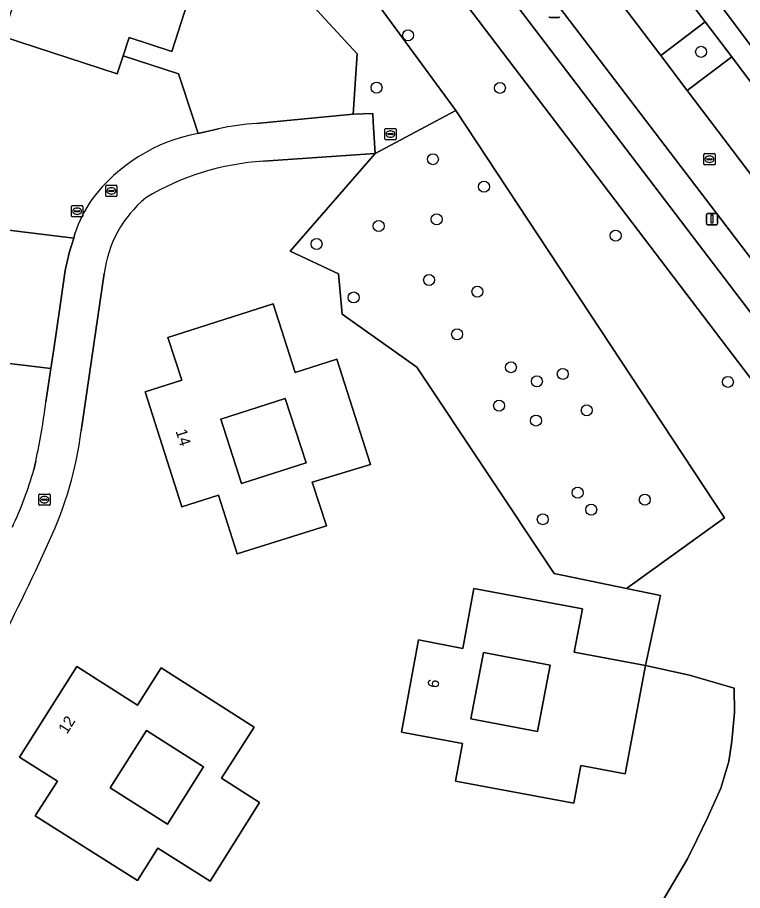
# Model space of a CAD drawing. Extents: x 156661 to 157576, y 383570 to 384425.
# Drawn here: x 156857.2 to 156921.7, y 384130.7 to 384208.3 of the extents above; entities that cross this region are included whole.
import ezdxf

# ---------------------------------------------------------------- set-up
doc = ezdxf.new("R2010")
doc.units = 0
for name, color, linetype in [('IMGEO_Berm_groen', 7, 'Continuous'), ('IMGEO_Boom', 7, 'Continuous'), ('IMGEO_Brandkraan', 7, 'Continuous'), ('IMGEO_Erf', 7, 'Continuous'), ('IMGEO_Fietspad_gesloten', 7, 'Continuous'), ('IMGEO_Groenvoorziening', 7, 'Continuous'), ('IMGEO_Lichtmast', 7, 'Continuous'), ('IMGEO_Loofbos', 7, 'Continuous'), ('IMGEO_Pand', 7, 'Continuous'), ('IMGEO_Pand_nummerreeks', 7, 'Continuous'), ('IMGEO_Parkeervlak_open', 7, 'Continuous'), ('IMGEO_Rijbaan_lokaal_gesloten', 7, 'Continuous'), ('IMGEO_Rioolput', 7, 'Continuous'), ('IMGEO_Voetpad_open', 7, 'Continuous')]:
    doc.layers.add(name, color=color, linetype=linetype)

msp = doc.modelspace()

# ---------------------------------------------------------------- linework, layer by layer
at = {"layer": 'IMGEO_Berm_groen'}
msp.add_lwpolyline([(156867.867, 384253.653), (156927.81, 384174.952), (156945.927, 384151.336), (156948.198, 384153.058), (156947.883, 384153.474), (156869.636, 384256.091)], dxfattribs=at)
msp.add_lwpolyline([(156918.348, 384207.896), (156914.397, 384204.906), (156916.761, 384201.782), (156920.708, 384204.77)], close=True, dxfattribs=at)
at = {"layer": 'IMGEO_Boom'}
for centre in [(156891.939, 384206.689), (156917.988, 384205.227), (156889.136, 384202.044), (156900.103, 384202.022), (156894.148, 384195.688), (156898.69, 384193.242), (156889.319, 384189.747), (156894.485, 384190.346), (156910.399, 384188.893), (156883.802, 384188.145), (156893.807, 384184.951), (156887.103, 384183.396), (156898.103, 384183.916), (156896.299, 384180.124), (156901.082, 384177.196), (156905.693, 384176.603), (156903.39, 384175.94), (156920.375, 384175.898), (156900.031, 384173.783), (156907.826, 384173.368), (156903.311, 384172.461), (156907.022, 384166.05), (156912.986, 384165.427), (156908.22, 384164.535), (156903.918, 384163.688)]:
    msp.add_circle(centre, 0.489, dxfattribs=at)
at = {"layer": 'IMGEO_Brandkraan'}
for p, q in [((156862.015, 384190.633), (156862.015, 384191.485)), ((156862.09, 384191.559), (156862.942, 384191.559)), ((156862.274, 384191.053), (156862.274, 384191.065)), ((156862.712, 384191.016), (156862.314, 384191.016)), ((156862.317, 384191.102), (156862.715, 384191.102)), ((156862.503, 384191.339), (156862.528, 384191.339)), ((156862.758, 384191.065), (156862.758, 384191.053)), ((156863.016, 384191.485), (156863.016, 384190.633)), ((156862.942, 384190.559), (156862.09, 384190.559)), ((156862.526, 384190.779), (156862.501, 384190.779))]:
    msp.add_line(p, q, dxfattribs=at)
for points in [[(156862.015, 384190.633), (156862.015, 384191.485)], [(156862.09, 384191.559), (156862.942, 384191.559)], [(156863.016, 384191.485), (156863.016, 384190.633)], [(156862.942, 384190.559), (156862.09, 384190.559)]]:
    msp.add_lwpolyline(points, dxfattribs=at)
for centre, radius, start, end in [((156862.092, 384191.483), 0.0765, 91.55205, 178.44795), ((156862.092, 384191.483), 0.0765, 91.55205, 178.44795), ((156862.314, 384191.062), 0.0403, 85.87752, 175.75265), ((156862.311, 384191.052), 0.0366, 178.93798, 274.71019), ((156862.715, 384191.059), 0.043, 264.86636, 352.45326), ((156862.719, 384191.064), 0.0386, 1.73085, 96.63898), ((156862.94, 384191.483), 0.0765, 1.55205, 88.44795), ((156862.94, 384191.483), 0.0765, 1.55205, 88.44795), ((156862.092, 384190.635), 0.0765, 181.55205, 268.44795), ((156862.092, 384190.635), 0.0765, 181.55205, 268.44795), ((156862.94, 384190.635), 0.0765, 271.55205, 358.44795), ((156862.94, 384190.635), 0.0765, 271.55205, 358.44795)]:
    msp.add_arc(centre, radius, start, end, dxfattribs=at)
for centre, major_axis, ratio, start_param, end_param in [((156862.502, 384191.059), (-0.387, 0.002), 0.722429, 4.712389, 7.853982), ((156862.527, 384191.059), (-0.39, 0.002), 0.717154, 1.570796, 4.712389)]:
    msp.add_ellipse(centre, major_axis=major_axis, ratio=ratio, start_param=start_param, end_param=end_param, dxfattribs=at)
at = {"layer": 'IMGEO_Erf'}
for points in [[(156873.961, 384214.559), (156872.032, 384208.65), (156870.925, 384205.255), (156867.13, 384206.495), (156866.597, 384204.873), (156871.527, 384203.266), (156872.855, 384199.253), (156873.276, 384197.981), (156875.087, 384198.385)], [(156878.469, 384198.871), (156880.897, 384199.085), (156887.053, 384199.698), (156887.401, 384205.04), (156880.686, 384212.359), (156873.961, 384214.559)], [(156913.042, 384150.679), (156914.369, 384156.907), (156911.353, 384157.536), (156904.931, 384158.876), (156892.709, 384177.194), (156886.083, 384181.928), (156885.768, 384185.506), (156881.456, 384187.505), (156889.009, 384196.195), (156879.074, 384195.504)], [(156864.923, 384185.542), (156862.886, 384171.545)], [(156911.232, 384109.029), (156911.053, 384109.423), (156910.897, 384109.877), (156909.839, 384114.445), (156909.514, 384116.775), (156909.382, 384117.878), (156909.426, 384118.952), (156909.558, 384119.746), (156910.294, 384122.041), (156911.324, 384124.31), (156916.768, 384133.516), (156917.618, 384135.197), (156918.56, 384137.15), (156919.737, 384139.785), (156920.467, 384142.161), (156920.715, 384143.965), (156920.951, 384146.515), (156920.928, 384148.664), (156916.959, 384149.844), (156913.042, 384150.679)]]:
    msp.add_lwpolyline(points, dxfattribs=at)
for points in [[(156862.225, 384188.659), (156855.43, 384189.495), (156854.647, 384183.209), (156854.186, 384179.514), (156850.228, 384180.007), (156850.013, 384178.291), (156860.187, 384177.083), (156860.435, 384178.797), (156860.969, 384182.483), (156861.466, 384185.786), (156861.796, 384187.367)], [(156876.751, 384160.602), (156875.084, 384165.84), (156871.829, 384164.801), (156868.572, 384175.009), (156871.827, 384176.044), (156870.583, 384179.841), (156879.937, 384182.83), (156881.895, 384176.737), (156885.611, 384177.916), (156888.599, 384168.555), (156883.415, 384166.995), (156884.673, 384163.097)], [(156882.865, 384168.698), (156881.016, 384174.427), (156875.293, 384172.58), (156877.142, 384166.851)], [(156896.154, 384140.409), (156896.776, 384143.771), (156891.354, 384144.753), (156892.871, 384152.959), (156896.804, 384152.211), (156897.796, 384157.534), (156907.432, 384155.736), (156906.712, 384151.876), (156913.042, 384150.679), (156911.225, 384141.066), (156907.289, 384141.798), (156906.669, 384138.463)], [(156898.652, 384151.859), (156897.528, 384145.952), (156903.443, 384144.827), (156904.567, 384150.734)], [(156875.351, 384140.668), (156878.732, 384138.517), (156874.338, 384131.527), (156869.687, 384134.452), (156867.875, 384131.591), (156858.8, 384137.317), (156860.766, 384140.413), (156857.394, 384142.547), (156862.49, 384150.597), (156867.874, 384147.177), (156869.985, 384150.476), (156878.247, 384145.221)], [(156870.54, 384136.603), (156873.766, 384141.676), (156868.688, 384144.906), (156865.461, 384139.833)]]:
    msp.add_lwpolyline(points, close=True, dxfattribs=at)
for centre, radius, start, end in [((156880.252, 384174.455), 24.481, 94.17602, 102.17905), ((156880.467, 384172.559), 22.987, 93.47345, 121.04804), ((156875.318, 384184.198), 10.481, 129.78358, 172.63482), ((156830.416, 384175.686), 32.733, 334.78913, 352.73266), ((156700.922, 384232.989), 174.332, 332.10301, 335.87805)]:
    msp.add_arc(centre, radius, start, end, dxfattribs=at)
at = {"layer": 'IMGEO_Fietspad_gesloten'}
for points in [[(156867.867, 384253.653), (156865.71, 384256.504), (156841.833, 384287.919), (156840.64, 384289.505), (156837.709, 384287.416), (156838.979, 384285.829), (156848.127, 384273.808), (156849.254, 384272.327), (156925.032, 384172.754), (156949.045, 384141.371)], [(156950.51, 384145.361), (156946.909, 384150.056), (156945.927, 384151.336), (156927.81, 384174.952), (156867.867, 384253.653)]]:
    msp.add_lwpolyline(points, dxfattribs=at)
at = {"layer": 'IMGEO_Groenvoorziening'}
for points in [[(156949.045, 384141.371), (156925.032, 384172.754), (156849.254, 384272.327)], [(156848.981, 384271.579), (156849.06, 384268.625), (156849.604, 384262.282), (156851.427, 384260.941), (156896.18, 384200.013), (156920.073, 384163.8), (156911.353, 384157.536), (156914.369, 384156.907), (156913.042, 384150.679), (156916.959, 384149.844), (156920.928, 384148.664), (156920.951, 384146.515), (156920.715, 384143.965), (156920.467, 384142.161), (156919.737, 384139.785), (156918.56, 384137.15), (156917.618, 384135.197), (156916.768, 384133.516), (156911.324, 384124.31)], [(156879.806, 384262.53), (156939.02, 384183.696)], [(156854.296, 384219.378), (156858.108, 384218.134), (156859.786, 384223.277), (156869.084, 384220.243), (156867.877, 384216.545), (156873.961, 384214.559), (156880.686, 384212.359), (156887.401, 384205.04), (156887.053, 384199.698), (156888.801, 384199.741), (156888.846, 384198.97), (156889.009, 384196.195), (156896.18, 384200.013), (156851.427, 384260.941)], [(156873.276, 384197.981), (156872.855, 384199.253), (156871.527, 384203.266), (156866.597, 384204.873), (156866.069, 384203.268), (156855.917, 384206.59)], [(156859.745, 384174.109), (156860.187, 384177.083), (156850.013, 384178.291), (156849.805, 384176.629), (156839.204, 384177.937), (156839.62, 384181.311), (156834.165, 384181.975), (156835.167, 384190.214), (156839.154, 384189.729), (156839.855, 384195.355), (156849.56, 384194.146), (156849.079, 384190.286), (156855.43, 384189.495), (156862.225, 384188.659), (156862.308, 384189.069)], [(156858.67, 384168.076), (156858.839, 384168.84)]]:
    msp.add_lwpolyline(points, dxfattribs=at)
for centre, radius, start, end in [((156876.099, 384182.888), 15.355, 100.59367, 143.05005), ((156874.161, 384185.063), 12.512, 145.67788, 161.3274), ((156797.327, 384182.129), 62.932, 347.80895, 352.67795), ((156824.03, 384178.186), 36.085, 335.09667, 343.72952)]:
    msp.add_arc(centre, radius, start, end, dxfattribs=at)
at = {"layer": 'IMGEO_Lichtmast'}
for p, q in [((156905.343, 384208.281), (156904.553, 384208.281)), ((156904.553, 384208.281), (156905.343, 384208.281)), ((156918.561, 384190.862), (156919.351, 384190.862)), ((156919.351, 384190.862), (156918.561, 384190.862)), ((156918.461, 384189.962), (156918.461, 384190.762)), ((156918.461, 384190.762), (156918.461, 384189.962)), ((156919.451, 384190.762), (156919.451, 384189.962)), ((156919.451, 384189.962), (156919.451, 384190.762)), ((156919.351, 384189.862), (156918.561, 384189.862)), ((156918.561, 384189.862), (156919.351, 384189.862))]:
    msp.add_line(p, q, dxfattribs=at)
msp.add_lwpolyline([(156918.881, 384190.737), (156919.031, 384190.737), (156919.031, 384189.987), (156918.881, 384189.987), (156918.881, 384190.737)], dxfattribs=at)
for centre, start, end in [((156904.553, 384208.381), 180, 270), ((156904.553, 384208.381), 180, 270), ((156905.343, 384208.381), 270, 0), ((156905.343, 384208.381), 270, 0), ((156918.561, 384190.762), 90, 180), ((156918.561, 384190.762), 90, 180), ((156919.351, 384190.762), 0, 90), ((156919.351, 384190.762), 360, 90), ((156918.561, 384189.962), 180, 270), ((156918.561, 384189.962), 180, 270), ((156919.351, 384189.962), 270, 0), ((156919.351, 384189.962), 270, 0)]:
    msp.add_arc(centre, 0.1, start, end, dxfattribs=at)
at = {"layer": 'IMGEO_Loofbos'}
msp.add_lwpolyline([(156881.456, 384187.505), (156885.768, 384185.506), (156886.083, 384181.928), (156892.709, 384177.194), (156904.931, 384158.876), (156911.353, 384157.536), (156920.073, 384163.8), (156896.18, 384200.013), (156889.009, 384196.195)], close=True, dxfattribs=at)
at = {"layer": 'IMGEO_Pand'}
for points in [[(156873.961, 384214.559), (156867.877, 384216.545), (156869.084, 384220.243), (156859.786, 384223.277), (156858.108, 384218.134), (156854.296, 384219.378), (156851.734, 384211.527), (156856.974, 384209.822), (156855.917, 384206.59), (156866.069, 384203.268), (156866.597, 384204.873), (156867.13, 384206.495), (156870.925, 384205.255), (156872.032, 384208.65)], [(156885.611, 384177.916), (156881.895, 384176.737), (156879.937, 384182.83), (156870.583, 384179.841), (156871.827, 384176.044), (156868.572, 384175.009), (156871.829, 384164.801), (156875.084, 384165.84), (156876.751, 384160.602), (156884.673, 384163.097), (156883.415, 384166.995), (156888.599, 384168.555)], [(156882.865, 384168.698), (156877.142, 384166.851), (156875.293, 384172.58), (156881.016, 384174.427)], [(156913.042, 384150.679), (156906.712, 384151.876), (156907.432, 384155.736), (156897.796, 384157.534), (156896.804, 384152.211), (156892.871, 384152.959), (156891.354, 384144.753), (156896.776, 384143.771), (156896.154, 384140.409), (156906.669, 384138.463), (156907.289, 384141.798), (156911.225, 384141.066)], [(156898.652, 384151.859), (156904.567, 384150.734), (156903.443, 384144.827), (156897.528, 384145.952)], [(156878.247, 384145.221), (156869.985, 384150.476), (156867.874, 384147.177), (156862.49, 384150.597), (156857.394, 384142.547), (156860.766, 384140.413), (156858.8, 384137.317), (156867.875, 384131.591), (156869.687, 384134.452), (156874.338, 384131.527), (156878.732, 384138.517), (156875.351, 384140.668)], [(156870.54, 384136.603), (156865.461, 384139.833), (156868.688, 384144.906), (156873.766, 384141.676)]]:
    msp.add_lwpolyline(points, close=True, dxfattribs=at)
at = {"layer": 'IMGEO_Parkeervlak_open'}
for points in [[(156914.397, 384204.906), (156918.348, 384207.896), (156909.04, 384220.251), (156905.044, 384217.212)], [(156926.719, 384196.787), (156920.708, 384204.77), (156916.761, 384201.782), (156922.806, 384193.826)]]:
    msp.add_lwpolyline(points, close=True, dxfattribs=at)
at = {"layer": 'IMGEO_Rijbaan_lokaal_gesloten'}
for points in [[(156876.48, 384254.755), (156868.186, 384265.651), (156860.937, 384275.173), (156857.345, 384272.328), (156868.344, 384257.78), (156869.636, 384256.091), (156947.883, 384153.474), (156948.198, 384153.058), (156949.137, 384151.82), (156967.768, 384127.243)], [(156978.939, 384120.025), (156978.024, 384121.227), (156977.753, 384121.583), (156976.126, 384123.722), (156968.544, 384133.691), (156965.332, 384137.913), (156955.947, 384150.252), (156954.053, 384152.742), (156952.237, 384155.208), (156949.248, 384159.24), (156941.651, 384169.047), (156938.611, 384173.044), (156935.139, 384177.608), (156933.628, 384179.594), (156922.806, 384193.826), (156916.761, 384201.782), (156914.397, 384204.906), (156905.044, 384217.212), (156901.645, 384221.683), (156891.001, 384235.643), (156888.996, 384238.303), (156878.44, 384252.173), (156876.735, 384254.42)], [(156879.074, 384195.504), (156889.009, 384196.195), (156888.846, 384198.97), (156888.801, 384199.741), (156887.053, 384199.698), (156880.897, 384199.085), (156878.469, 384198.871)], [(156875.087, 384198.385), (156873.276, 384197.981)], [(156862.308, 384189.069), (156862.225, 384188.659), (156861.796, 384187.367), (156861.466, 384185.786), (156860.969, 384182.483), (156860.435, 384178.797), (156860.187, 384177.083), (156859.745, 384174.109)], [(156862.886, 384171.545), (156864.923, 384185.542)], [(156858.839, 384168.84), (156858.67, 384168.076)]]:
    msp.add_lwpolyline(points, dxfattribs=at)
for centre, radius, start, end in [((156880.252, 384174.455), 24.481, 94.17602, 102.17905), ((156876.099, 384182.888), 15.355, 100.59367, 143.05005), ((156880.467, 384172.559), 22.987, 93.47345, 121.04804), ((156874.161, 384185.063), 12.512, 145.67788, 161.3274), ((156875.318, 384184.198), 10.481, 129.78358, 172.63482), ((156797.327, 384182.129), 62.932, 347.80895, 352.67795), ((156830.416, 384175.686), 32.733, 334.78913, 352.73266), ((156824.03, 384178.186), 36.085, 335.09667, 343.72952), ((156700.922, 384232.989), 174.332, 332.10301, 335.87805)]:
    msp.add_arc(centre, radius, start, end, dxfattribs=at)
at = {"layer": 'IMGEO_Rioolput'}
for p, q in [((156889.867, 384197.491), (156889.867, 384198.343)), ((156889.942, 384198.417), (156890.794, 384198.417)), ((156890.126, 384197.911), (156890.126, 384197.923)), ((156890.564, 384197.874), (156890.166, 384197.874)), ((156890.169, 384197.96), (156890.567, 384197.96)), ((156890.355, 384198.197), (156890.38, 384198.197)), ((156890.61, 384197.923), (156890.61, 384197.911)), ((156890.868, 384198.343), (156890.868, 384197.491)), ((156890.794, 384197.417), (156889.942, 384197.417)), ((156890.378, 384197.637), (156890.353, 384197.637)), ((156918.234, 384195.255), (156918.234, 384196.107)), ((156918.309, 384196.181), (156919.161, 384196.181)), ((156918.493, 384195.675), (156918.493, 384195.687)), ((156918.931, 384195.638), (156918.533, 384195.638)), ((156918.536, 384195.724), (156918.934, 384195.724)), ((156918.722, 384195.961), (156918.747, 384195.961)), ((156918.977, 384195.687), (156918.977, 384195.675)), ((156919.235, 384196.107), (156919.235, 384195.255)), ((156919.161, 384195.181), (156918.309, 384195.181)), ((156918.745, 384195.401), (156918.72, 384195.401)), ((156865.059, 384192.443), (156865.059, 384193.295)), ((156865.134, 384193.369), (156865.986, 384193.369)), ((156866.06, 384193.295), (156866.06, 384192.443)), ((156865.318, 384192.863), (156865.318, 384192.875)), ((156865.756, 384192.826), (156865.358, 384192.826)), ((156865.361, 384192.912), (156865.759, 384192.912)), ((156865.57, 384192.589), (156865.545, 384192.589)), ((156865.547, 384193.149), (156865.572, 384193.149)), ((156865.802, 384192.875), (156865.802, 384192.863)), ((156865.986, 384192.369), (156865.134, 384192.369)), ((156859.107, 384165.002), (156859.107, 384165.854)), ((156859.182, 384165.928), (156860.034, 384165.928)), ((156859.366, 384165.422), (156859.366, 384165.434)), ((156859.804, 384165.385), (156859.406, 384165.385)), ((156859.409, 384165.471), (156859.807, 384165.471)), ((156859.595, 384165.708), (156859.62, 384165.708)), ((156859.85, 384165.434), (156859.85, 384165.422)), ((156860.108, 384165.854), (156860.108, 384165.002)), ((156860.034, 384164.928), (156859.182, 384164.928)), ((156859.618, 384165.148), (156859.593, 384165.148))]:
    msp.add_line(p, q, dxfattribs=at)
for points in [[(156889.867, 384197.491), (156889.867, 384198.343)], [(156889.942, 384198.417), (156890.794, 384198.417)], [(156890.868, 384198.343), (156890.868, 384197.491)], [(156890.794, 384197.417), (156889.942, 384197.417)], [(156918.234, 384195.255), (156918.234, 384196.107)], [(156918.309, 384196.181), (156919.161, 384196.181)], [(156919.235, 384196.107), (156919.235, 384195.255)], [(156919.161, 384195.181), (156918.309, 384195.181)], [(156865.059, 384192.443), (156865.059, 384193.295)], [(156865.134, 384193.369), (156865.986, 384193.369)], [(156866.06, 384193.295), (156866.06, 384192.443)], [(156865.986, 384192.369), (156865.134, 384192.369)], [(156859.107, 384165.002), (156859.107, 384165.854)], [(156859.182, 384165.928), (156860.034, 384165.928)], [(156860.108, 384165.854), (156860.108, 384165.002)], [(156860.034, 384164.928), (156859.182, 384164.928)]]:
    msp.add_lwpolyline(points, dxfattribs=at)
for centre, radius, start, end in [((156889.944, 384198.341), 0.0765, 91.55205, 178.44795), ((156889.944, 384198.341), 0.0765, 91.55205, 178.44795), ((156890.166, 384197.92), 0.0403, 85.87752, 175.75265), ((156890.163, 384197.91), 0.0366, 178.93798, 274.71019), ((156890.567, 384197.917), 0.043, 264.86636, 352.45326), ((156890.571, 384197.922), 0.0386, 1.73085, 96.63898), ((156890.792, 384198.341), 0.0765, 1.55205, 88.44795), ((156890.792, 384198.341), 0.0765, 1.55205, 88.44795), ((156889.944, 384197.493), 0.0765, 181.55205, 268.44795), ((156889.944, 384197.493), 0.0765, 181.55205, 268.44795), ((156890.792, 384197.493), 0.0765, 271.55205, 358.44795), ((156890.792, 384197.493), 0.0765, 271.55205, 358.44795), ((156918.311, 384196.105), 0.0765, 91.55205, 178.44795), ((156918.311, 384196.105), 0.0765, 91.55205, 178.44795), ((156918.533, 384195.684), 0.0403, 85.87752, 175.75265), ((156918.53, 384195.674), 0.0366, 178.93798, 274.71019), ((156918.934, 384195.681), 0.043, 264.86636, 352.45326), ((156918.938, 384195.686), 0.0386, 1.73085, 96.63898), ((156919.159, 384196.105), 0.0765, 1.55205, 88.44795), ((156919.159, 384196.105), 0.0765, 1.55205, 88.44795), ((156918.311, 384195.257), 0.0765, 181.55205, 268.44795), ((156918.311, 384195.257), 0.0765, 181.55205, 268.44795), ((156919.159, 384195.257), 0.0765, 271.55205, 358.44795), ((156919.159, 384195.257), 0.0765, 271.55205, 358.44795), ((156865.136, 384193.293), 0.0765, 91.55205, 178.44795), ((156865.136, 384193.293), 0.0765, 91.55205, 178.44795), ((156865.984, 384193.293), 0.0765, 1.55205, 88.44795), ((156865.984, 384193.293), 0.0765, 1.55205, 88.44795), ((156865.136, 384192.445), 0.0765, 181.55205, 268.44795), ((156865.136, 384192.445), 0.0765, 181.55205, 268.44795), ((156865.358, 384192.872), 0.0403, 85.87752, 175.75265), ((156865.355, 384192.862), 0.0366, 178.93798, 274.71019), ((156865.759, 384192.869), 0.043, 264.86636, 352.45326), ((156865.763, 384192.874), 0.0386, 1.73085, 96.63898), ((156865.984, 384192.445), 0.0765, 271.55205, 358.44795), ((156865.984, 384192.445), 0.0765, 271.55205, 358.44795), ((156859.184, 384165.852), 0.0765, 91.55205, 178.44795), ((156859.184, 384165.852), 0.0765, 91.55205, 178.44795), ((156859.406, 384165.431), 0.0403, 85.87752, 175.75265), ((156859.403, 384165.421), 0.0366, 178.93798, 274.71019), ((156859.807, 384165.428), 0.043, 264.86636, 352.45326), ((156859.811, 384165.433), 0.0386, 1.73085, 96.63898), ((156860.032, 384165.852), 0.0765, 1.55205, 88.44795), ((156860.032, 384165.852), 0.0765, 1.55205, 88.44795), ((156859.184, 384165.004), 0.0765, 181.55205, 268.44795), ((156859.184, 384165.004), 0.0765, 181.55205, 268.44795), ((156860.032, 384165.004), 0.0765, 271.55205, 358.44795), ((156860.032, 384165.004), 0.0765, 271.55205, 358.44795)]:
    msp.add_arc(centre, radius, start, end, dxfattribs=at)
for centre, major_axis, ratio, start_param, end_param in [((156890.354, 384197.917), (-0.387, 0.002), 0.722429, 4.712389, 7.853982), ((156890.379, 384197.917), (-0.39, 0.002), 0.717154, 1.570796, 4.712389), ((156918.721, 384195.681), (-0.387, 0.002), 0.722429, 4.712389, 7.853982), ((156918.746, 384195.681), (-0.39, 0.002), 0.717154, 1.570796, 4.712389), ((156865.546, 384192.869), (-0.387, 0.002), 0.722429, 4.712389, 7.853982), ((156865.571, 384192.869), (-0.39, 0.002), 0.717154, 1.570796, 4.712389), ((156859.594, 384165.428), (-0.387, 0.002), 0.722429, 4.712389, 7.853982), ((156859.619, 384165.428), (-0.39, 0.002), 0.717154, 1.570796, 4.712389)]:
    msp.add_ellipse(centre, major_axis=major_axis, ratio=ratio, start_param=start_param, end_param=end_param, dxfattribs=at)
at = {"layer": 'IMGEO_Voetpad_open'}
for points in [[(156983.009, 384125.143), (156960.044, 384155.717), (156957.136, 384159.589), (156954.003, 384163.76), (156953.814, 384164.012), (156946.64, 384173.562), (156943.34, 384177.955), (156939.02, 384183.696), (156879.806, 384262.53), (156876.187, 384267.345), (156852.753, 384298.627)], [(156852.393, 384295.853), (156865.294, 384278.622), (156874.701, 384266.057), (156878.321, 384261.237), (156882.665, 384255.414), (156893.129, 384241.435), (156895.163, 384238.727), (156905.644, 384224.752), (156909.04, 384220.251), (156918.348, 384207.896), (156920.708, 384204.77), (156926.719, 384196.787), (156937.458, 384182.455), (156938.971, 384180.443), (156942.416, 384175.861), (156945.427, 384171.858), (156952.69, 384162.198), (156954.942, 384159.203), (156957.791, 384155.414), (156959.593, 384153.019), (156968.907, 384140.631), (156972.116, 384136.364), (156979.61, 384126.397)]]:
    msp.add_lwpolyline(points, dxfattribs=at)

# ---------------------------------------------------------------- texts
at = {"layer": 'IMGEO_Pand_nummerreeks'}
for s, rotation, p in [('14', 287.49792, (156871.262, 384171.523)), ('6', 79.32601, (156894.612, 384148.629)), ('12', 57.46767, (156861.61, 384144.539))]:
    msp.add_text(s, height=1, rotation=rotation, dxfattribs=at).set_placement(p)

doc.saveas('drawing.dxf')
